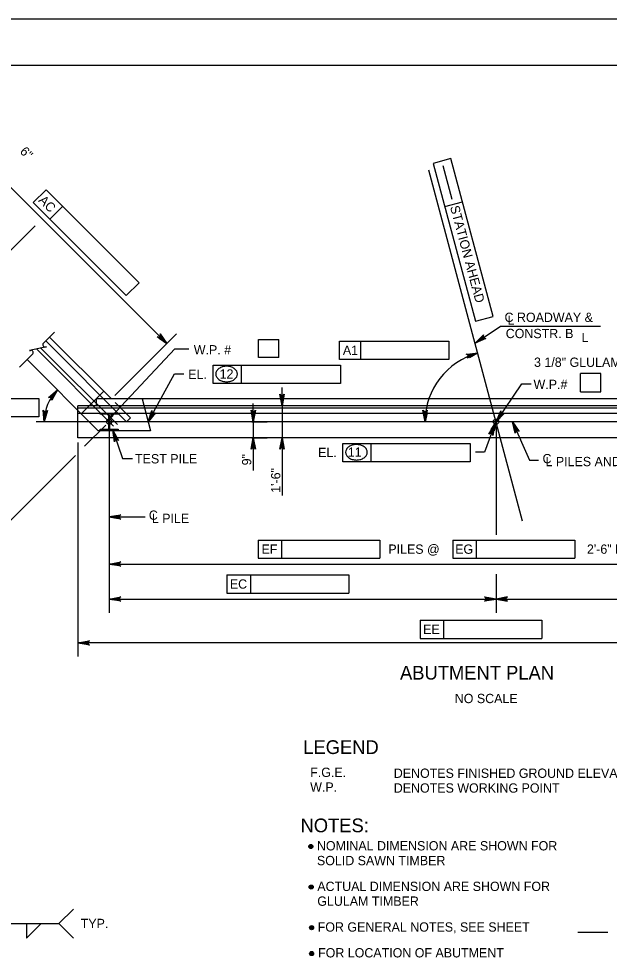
# Model space of a CAD drawing. Extents: x 638304 to 640306, y 296653 to 298435.
# Drawn here: x 639455.2 to 639645.7, y 298131.6 to 298435.5 of the extents above; entities that cross this region are included whole.
import ezdxf

# ---------------------------------------------------------------- set-up
doc = ezdxf.new("R2010")
doc.units = 0
for name, color, linetype in [('2', 7, 'Continuous'), ('3', 7, 'Continuous'), ('4', 7, 'Continuous'), ('5', 7, 'Continuous'), ('Level 2', 7, 'Continuous'), ('Level 3', 7, 'Continuous'), ('Level 4', 7, 'Continuous'), ('Level 5', 7, 'Continuous'), ('Level 6', 7, 'Continuous'), ('Level 8', 7, 'Continuous'), ('PLT-BNDY', 7, 'Continuous')]:
    doc.layers.add(name, color=color, linetype=linetype)

# ---------------------------------------------------------------- blocks, each defined once
blk = doc.blocks.new('HPILE')
at = {"layer": '3'}
for p, q in [((-0.12, -2.66), (-0.12, 2.66)), ((0.12, 2.66), (0.12, -2.66)), ((-3.67, -3.1), (-0.56, -3.1))]:
    blk.add_line(p, q, dxfattribs=at)
for points in [[(-0.56, 3.1), (-3.67, 3.1), (-3.67, 3.54), (3.67, 3.54), (3.67, 3.1), (0.56, 3.1)], [(0.56, -3.1), (3.67, -3.1), (3.67, -3.54), (-3.67, -3.54), (-3.67, -3.1)]]:
    blk.add_lwpolyline(points, dxfattribs=at)
for centre, start, end in [((-0.56, 2.66), 0, 90), ((0.56, 2.66), 90, 180), ((-0.56, -2.66), 270, 0), ((0.56, -2.66), 180, 270)]:
    blk.add_arc(centre, 0.438, start, end, dxfattribs=at)

msp = doc.modelspace()

# ---------------------------------------------------------------- linework, layer by layer
at = {"layer": '2'}
msp.add_line((639316.46, 298420.46), (640102.46, 298420.46), dxfattribs=at)
at = {"layer": 'Level 2'}
for p, q in [((639485.08, 298312.79), (639465.12, 298332.75)), ((639480.8, 298302.48), (639457.82, 298325.46)), ((639482.64, 298315.23), (639475.35, 298307.93)), ((639731.17, 298312.79), (639485.08, 298312.79)), ((639494.95, 298312.79), (639497.71, 298302.48)), ((639474.26, 298300.27), (639474.26, 298309.02)), ((639489.95, 298305.43), (639491.17, 298306.64)), ((639743.13, 298300.27), (639474.26, 298300.27)), ((639497.71, 298302.48), (639480.8, 298302.48))]:
    msp.add_line(p, q, dxfattribs=at)
at = {"layer": 'Level 3'}
for p, q in [((639489.95, 298305.43), (639463.9, 298331.54)), ((639480.2, 298310.58), (639480.2, 298312.79)), ((639485.08, 298312.79), (639480.2, 298312.79)), ((639474.26, 298309.02), (639474.26, 298310.58)), ((639743.13, 298310.58), (639474.26, 298310.58)), ((639474.26, 298309.93), (639743.13, 298309.93)), ((639486.22, 298311.65), (639491.17, 298306.64)), ((639474.26, 298308.21), (639743.13, 298308.21)), ((639468.07, 298143.43), (639472.77, 298148.13)), ((639438.49, 298143.44), (639468.07, 298143.44)), ((639457.64, 298143.44), (639457.64, 298138.74)), ((639457.64, 298138.74), (639462.34, 298143.44)), ((639468.07, 298143.43), (639472.77, 298138.74))]:
    msp.add_line(p, q, dxfattribs=at)
msp.add_circle((639609.2, 298305.43), 0.849, dxfattribs=at)
at = {"layer": 'Level 4'}
for p, q in [((639502.92, 298330.64), (639443.7, 298389.87)), ((639594.61, 298390.33), (639588.91, 298388.8)), ((639588.91, 298388.8), (639602.57, 298337.85)), ((639595.09, 298377.11), (639592.16, 298388.03)), ((639608.26, 298339.38), (639594.61, 298390.33)), ((639464.01, 298380.29), (639459.84, 298376.12)), ((639464.01, 298380.29), (639494.02, 298350.28)), ((639459.84, 298376.12), (639489.85, 298346.11)), ((639592.64, 298374.91), (639598.33, 298376.44)), ((639469.35, 298374.95), (639465.18, 298370.78)), ((639444.8, 298353.07), (639460.41, 298368.69)), ((639494.02, 298350.28), (639489.85, 298346.11)), ((639602.57, 298337.85), (639608.26, 298339.38)), ((639602.44, 298330.81), (639610.62, 298336.28)), ((639610.62, 298336.28), (639642.86, 298336.28)), ((639486.16, 298313.88), (639506.05, 298333.77)), ((639532.56, 298332), (639539.14, 298332)), ((639532.56, 298326.1), (639532.56, 298332)), ((639539.14, 298326.1), (639539.14, 298332)), ((639558.71, 298331.4), (639593.95, 298331.4)), ((639558.71, 298325.51), (639558.71, 298331.4)), ((639565.54, 298325.51), (639565.54, 298331.4)), ((639593.95, 298331.4), (639593.95, 298325.51)), ((639485.76, 298304), (639460.88, 298328.89)), ((639486.99, 298304.52), (639462.29, 298329.21)), ((639486.16, 298313.88), (639497.84, 298325.56)), ((639539.14, 298326.1), (639532.56, 298326.1)), ((639593.95, 298325.51), (639558.71, 298325.51)), ((639517.88, 298323.64), (639559.01, 298323.64)), ((639517.88, 298317.75), (639517.88, 298323.64)), ((639527.03, 298317.75), (639527.03, 298323.64)), ((639559.01, 298323.64), (639559.01, 298317.75)), ((639496.93, 298305.4), (639505.47, 298320.86)), ((639505.47, 298320.86), (639508.42, 298320.86)), ((639643.06, 298320.93), (639636.48, 298320.93)), ((639636.48, 298315.04), (639636.48, 298320.93)), ((639643.06, 298315.04), (639643.06, 298320.93)), ((639559.01, 298317.75), (639517.88, 298317.75)), ((639540.14, 298313.53), (639540.14, 298316.48)), ((639636.48, 298315.04), (639643.06, 298315.04)), ((639426.36, 298312.93), (639461.6, 298312.93)), ((639461.6, 298312.93), (639461.6, 298307.03)), ((639530.86, 298308.37), (639530.86, 298311.32)), ((639539.57, 298310.58), (639535.72, 298310.58)), ((639540.14, 298310.58), (639540.14, 298300.27)), ((639461.6, 298307.03), (639426.36, 298307.03)), ((639755.33, 298305.43), (639460.73, 298305.43)), ((639483.26, 298304.34), (639476.42, 298297.5)), ((639484.34, 298303.89), (639484.34, 298243.75)), ((639530.36, 298305.43), (639535.28, 298305.43)), ((639530.86, 298305.43), (639530.86, 298300.27)), ((639608.84, 298304.66), (639605.46, 298295.62)), ((639609.21, 298303.89), (639609.21, 298268.88)), ((639530.36, 298300.27), (639535.28, 298300.27)), ((639539.57, 298300.27), (639535.72, 298300.27)), ((639474.26, 298298.73), (639474.26, 298229.63)), ((639530.86, 298297.32), (639530.86, 298289.66)), ((639540.14, 298297.32), (639540.14, 298281.64)), ((639559.77, 298298.4), (639600.9, 298298.4)), ((639559.77, 298292.51), (639559.77, 298298.4)), ((639568.92, 298292.51), (639568.92, 298298.4)), ((639600.9, 298298.4), (639600.9, 298292.51)), ((639473.45, 298294.53), (639445.7, 298266.78)), ((639605.46, 298295.62), (639602.52, 298295.62)), ((639600.9, 298292.51), (639559.77, 298292.51)), ((639484.34, 298274.68), (639495.93, 298274.68)), ((639532.39, 298267.23), (639532.39, 298261.34)), ((639532.39, 298267.23), (639571.68, 298267.23)), ((639539.93, 298267.23), (639539.93, 298261.34)), ((639571.68, 298267.23), (639571.68, 298261.34)), ((639595.28, 298267.23), (639634.58, 298267.23)), ((639595.28, 298267.23), (639595.28, 298261.34)), ((639602.83, 298267.23), (639602.83, 298261.34)), ((639634.58, 298267.23), (639634.58, 298261.34)), ((639532.39, 298261.34), (639571.68, 298261.34)), ((639595.28, 298261.34), (639634.58, 298261.34)), ((639484.34, 298259.48), (639731.9, 298259.48)), ((639522.35, 298255.98), (639561.65, 298255.98)), ((639522.35, 298255.98), (639522.35, 298250.08)), ((639529.9, 298255.98), (639529.9, 298250.08)), ((639561.65, 298255.98), (639561.65, 298250.08)), ((639609.21, 298256.17), (639609.21, 298243.75)), ((639484.34, 298248.17), (639606.26, 298248.17)), ((639522.35, 298250.08), (639561.65, 298250.08)), ((639612.15, 298248.17), (639731.9, 298248.17)), ((639584.67, 298241.36), (639623.96, 298241.36)), ((639584.67, 298241.36), (639584.67, 298235.46)), ((639592.21, 298241.36), (639592.21, 298235.46)), ((639623.96, 298241.36), (639623.96, 298235.46)), ((639743.13, 298234.05), (639474.26, 298234.05)), ((639584.67, 298235.46), (639623.96, 298235.46)), ((639635.64, 298140.62), (639645.28, 298140.62))]:
    msp.add_line(p, q, dxfattribs=at)
for points in [[(639502.92, 298330.64), (639499.8, 298332.78), (639500.14, 298332.72), (639500.43, 298332.79), (639500.63, 298332.94), (639500.78, 298333.14), (639500.85, 298333.43), (639500.79, 298333.77), (639502.92, 298330.64), (639500.85, 298333.43), (639500.78, 298333.14), (639502.92, 298330.64), (639500.63, 298332.94), (639500.43, 298332.79), (639502.92, 298330.64), (639500.14, 298332.72)], [(639602.44, 298330.81), (639605.14, 298333.46), (639605.02, 298333.14), (639605.03, 298332.85), (639605.13, 298332.62), (639605.31, 298332.43), (639605.57, 298332.31), (639605.92, 298332.3), (639602.44, 298330.81), (639605.57, 298332.31), (639605.31, 298332.43), (639602.44, 298330.81), (639605.13, 298332.62), (639605.03, 298332.85), (639602.44, 298330.81), (639605.02, 298333.14)], [(639483.45, 298305.43), (639505.54, 298328.9), (639510.03, 298328.9)], [(639603.31, 298327.52), (639599.9, 298325.89), (639600.12, 298326.16), (639600.2, 298326.44), (639600.18, 298326.69), (639600.07, 298326.92), (639599.87, 298327.13), (639599.54, 298327.24), (639603.31, 298327.52), (639599.87, 298327.13), (639600.07, 298326.92), (639603.31, 298327.52), (639600.18, 298326.69), (639600.2, 298326.44), (639603.31, 298327.52), (639600.12, 298326.16)], [(639467.61, 298315.68), (639465.81, 298312.34), (639465.84, 298312.69), (639465.74, 298312.96), (639465.57, 298313.15), (639465.35, 298313.27), (639465.06, 298313.32), (639464.73, 298313.22), (639467.61, 298315.68), (639465.06, 298313.32), (639465.35, 298313.27), (639467.61, 298315.68), (639465.57, 298313.15), (639465.74, 298312.96), (639467.61, 298315.68), (639465.84, 298312.69)], [(639609.21, 298305.43), (639617.51, 298317.63), (639620.53, 298317.63)], [(639540.14, 298310.58), (639539.44, 298314.31), (639539.64, 298314.02), (639539.89, 298313.87), (639540.14, 298313.83), (639540.39, 298313.87), (639540.64, 298314.02), (639540.84, 298314.31), (639540.14, 298310.58), (639540.64, 298314.02), (639540.39, 298313.87), (639540.14, 298310.58), (639540.14, 298313.83), (639539.89, 298313.87), (639540.14, 298310.58), (639539.64, 298314.02)], [(639463.36, 298305.43), (639463.06, 298309.2), (639463.23, 298308.89), (639463.46, 298308.72), (639463.7, 298308.65), (639463.96, 298308.67), (639464.22, 298308.79), (639464.45, 298309.05), (639463.36, 298305.43), (639464.22, 298308.79), (639463.96, 298308.67), (639463.36, 298305.43), (639463.7, 298308.65), (639463.46, 298308.72), (639463.36, 298305.43), (639463.23, 298308.89)], [(639496.93, 298305.4), (639498.11, 298309), (639498.15, 298308.65), (639498.3, 298308.4), (639498.5, 298308.24), (639498.73, 298308.16), (639499.02, 298308.17), (639499.34, 298308.32), (639496.93, 298305.4), (639499.02, 298308.17), (639498.73, 298308.16), (639496.93, 298305.4), (639498.5, 298308.24), (639498.3, 298308.4), (639496.93, 298305.4), (639498.15, 298308.65)], [(639530.86, 298305.43), (639530.16, 298309.15), (639530.36, 298308.86), (639530.61, 298308.71), (639530.86, 298308.67), (639531.11, 298308.71), (639531.36, 298308.86), (639531.56, 298309.15), (639530.86, 298305.43), (639531.36, 298308.86), (639531.11, 298308.71), (639530.86, 298305.43), (639530.86, 298308.67), (639530.61, 298308.71), (639530.86, 298305.43), (639530.36, 298308.86)], [(639586.3, 298305.43), (639585.61, 298309.15), (639585.81, 298308.86), (639586.06, 298308.71), (639586.3, 298308.67), (639586.55, 298308.71), (639586.8, 298308.86), (639587, 298309.15), (639586.3, 298305.43), (639586.8, 298308.86), (639586.55, 298308.71), (639586.3, 298305.43), (639586.3, 298308.67), (639586.06, 298308.71), (639586.3, 298305.43), (639585.81, 298308.86)], [(639609.21, 298305.43), (639610.72, 298308.89), (639610.73, 298308.55), (639610.85, 298308.28), (639611.03, 298308.11), (639611.26, 298308), (639611.55, 298307.99), (639611.87, 298308.11), (639609.21, 298305.43), (639611.55, 298307.99), (639611.26, 298308), (639609.21, 298305.43), (639611.03, 298308.11), (639610.85, 298308.28), (639609.21, 298305.43), (639610.73, 298308.55)], [(639608.84, 298304.66), (639608.19, 298300.93), (639608.11, 298301.27), (639607.92, 298301.49), (639607.7, 298301.62), (639607.45, 298301.67), (639607.17, 298301.62), (639606.88, 298301.42), (639608.84, 298304.66), (639607.17, 298301.62), (639607.45, 298301.67), (639608.84, 298304.66), (639607.7, 298301.62), (639607.92, 298301.49), (639608.84, 298304.66), (639608.11, 298301.27)], [(639614.56, 298305.43), (639619.97, 298293), (639622.91, 298293)], [(639614.56, 298305.43), (639616.68, 298302.29), (639616.39, 298302.47), (639616.1, 298302.51), (639615.85, 298302.45), (639615.64, 298302.31), (639615.47, 298302.08), (639615.4, 298301.73), (639614.56, 298305.43), (639615.47, 298302.08), (639615.64, 298302.31), (639614.56, 298305.43), (639615.85, 298302.45), (639616.1, 298302.51), (639614.56, 298305.43), (639616.39, 298302.47)], [(639485.52, 298302.65), (639488.62, 298293.55), (639491.83, 298293.55)], [(639485.52, 298302.65), (639487.38, 298299.35), (639487.1, 298299.56), (639486.82, 298299.62), (639486.57, 298299.58), (639486.34, 298299.46), (639486.16, 298299.24), (639486.06, 298298.9), (639485.52, 298302.65), (639486.16, 298299.24), (639486.34, 298299.46), (639485.52, 298302.65), (639486.57, 298299.58), (639486.82, 298299.62), (639485.52, 298302.65), (639487.1, 298299.56)], [(639530.86, 298300.27), (639531.56, 298296.55), (639531.36, 298296.83), (639531.11, 298296.98), (639530.86, 298297.02), (639530.61, 298296.98), (639530.36, 298296.83), (639530.16, 298296.55), (639530.86, 298300.27), (639530.36, 298296.83), (639530.61, 298296.98), (639530.86, 298300.27), (639530.86, 298297.02), (639531.11, 298296.98), (639530.86, 298300.27), (639531.36, 298296.83)], [(639540.14, 298300.27), (639540.84, 298296.55), (639540.64, 298296.83), (639540.39, 298296.98), (639540.14, 298297.02), (639539.89, 298296.98), (639539.64, 298296.83), (639539.44, 298296.55), (639540.14, 298300.27), (639539.64, 298296.83), (639539.89, 298296.98), (639540.14, 298300.27), (639540.14, 298297.02), (639540.39, 298296.98), (639540.14, 298300.27), (639540.64, 298296.83)], [(639484.34, 298274.68), (639488.06, 298275.38), (639487.78, 298275.18), (639487.63, 298274.93), (639487.59, 298274.68), (639487.63, 298274.43), (639487.78, 298274.19), (639488.06, 298273.99), (639484.34, 298274.68), (639487.78, 298274.19), (639487.63, 298274.43), (639484.34, 298274.68), (639487.59, 298274.68), (639487.63, 298274.93), (639484.34, 298274.68), (639487.78, 298275.18)], [(639484.34, 298259.48), (639488.06, 298260.18), (639487.78, 298259.98), (639487.63, 298259.73), (639487.59, 298259.48), (639487.63, 298259.23), (639487.78, 298258.98), (639488.06, 298258.78), (639484.34, 298259.48), (639487.78, 298258.98), (639487.63, 298259.23), (639484.34, 298259.48), (639487.59, 298259.48), (639487.63, 298259.73), (639484.34, 298259.48), (639487.78, 298259.98)], [(639484.34, 298248.17), (639488.06, 298248.87), (639487.78, 298248.67), (639487.63, 298248.42), (639487.59, 298248.17), (639487.63, 298247.92), (639487.78, 298247.67), (639488.06, 298247.47), (639484.34, 298248.17), (639487.78, 298247.67), (639487.63, 298247.92), (639484.34, 298248.17), (639487.59, 298248.17), (639487.63, 298248.42), (639484.34, 298248.17), (639487.78, 298248.67)], [(639609.21, 298248.17), (639605.48, 298247.47), (639605.77, 298247.67), (639605.92, 298247.92), (639605.96, 298248.17), (639605.92, 298248.42), (639605.77, 298248.67), (639605.48, 298248.87), (639609.21, 298248.17), (639605.77, 298248.67), (639605.92, 298248.42), (639609.21, 298248.17), (639605.96, 298248.17), (639605.92, 298247.92), (639609.21, 298248.17), (639605.77, 298247.67)], [(639609.21, 298248.17), (639612.93, 298247.47), (639612.64, 298247.67), (639612.49, 298247.92), (639612.45, 298248.17), (639612.49, 298248.42), (639612.64, 298248.67), (639612.93, 298248.87), (639609.21, 298248.17), (639612.64, 298248.67), (639612.49, 298248.42), (639609.21, 298248.17), (639612.45, 298248.17), (639612.49, 298247.92), (639609.21, 298248.17), (639612.64, 298247.67)], [(639474.26, 298234.05), (639477.98, 298234.75), (639477.7, 298234.55), (639477.55, 298234.3), (639477.5, 298234.05), (639477.55, 298233.8), (639477.7, 298233.55), (639477.98, 298233.35), (639474.26, 298234.05), (639477.7, 298233.55), (639477.55, 298233.8), (639474.26, 298234.05), (639477.5, 298234.05), (639477.55, 298234.3), (639474.26, 298234.05), (639477.7, 298234.55)]]:
    msp.add_lwpolyline(points, dxfattribs=at)
for points in [[(639501.19, 298333.07), (639500.49, 298332.38), (639502.92, 298330.64)], [(639604.61, 298332.86), (639605.16, 298332.04), (639602.44, 298330.81)], [(639600.61, 298326.09), (639600.3, 298327.02), (639603.25, 298327.5)], [(639539.64, 298313.53), (639540.63, 298313.53), (639540.14, 298310.58)], [(639483.45, 298305.43), (639485.65, 298307.41), (639485.29, 298307.74)], [(639497.88, 298308.15), (639498.74, 298307.68), (639496.89, 298305.34)], [(639530.37, 298308.37), (639531.35, 298308.37), (639530.86, 298305.43)], [(639586.01, 298308.4), (639586.98, 298308.33), (639586.3, 298305.43)], [(639609.21, 298305.43), (639611.07, 298307.73), (639610.66, 298308)], [(639608.56, 298302.51), (639607.65, 298302.88), (639609.21, 298305.43)], [(639614.56, 298305.43), (639615.51, 298302.62), (639615.96, 298302.82)], [(639485.52, 298302.65), (639486.24, 298299.78), (639486.7, 298299.94)], [(639530.37, 298297.32), (639531.35, 298297.32), (639530.86, 298300.27)], [(639539.64, 298297.32), (639540.63, 298297.32), (639540.14, 298300.27)], [(639487.29, 298274.19), (639487.29, 298275.17), (639484.34, 298274.68)], [(639487.29, 298259.97), (639487.29, 298258.99), (639484.34, 298259.48)], [(639487.29, 298248.66), (639487.29, 298247.68), (639484.34, 298248.17)], [(639606.26, 298248.66), (639606.26, 298247.68), (639609.21, 298248.17)], [(639612.15, 298248.66), (639612.15, 298247.68), (639609.21, 298248.17)], [(639477.21, 298234.54), (639477.21, 298233.56), (639474.26, 298234.05)]]:
    msp.add_lwpolyline(points, close=True, dxfattribs=at)
for centre, radius in [((639484.34, 298305.43), 0.849), ((639549.41, 298168.32), 0.665), ((639549.41, 298168.32), 0.499), ((639549.41, 298168.32), 0.333), ((639549.41, 298168.32), 0.166), ((639549.54, 298155.22), 0.665), ((639549.54, 298155.22), 0.499), ((639549.54, 298155.22), 0.333), ((639549.54, 298155.22), 0.166), ((639549.66, 298142.11), 0.665), ((639549.66, 298142.11), 0.499), ((639549.66, 298142.11), 0.333), ((639549.66, 298142.11), 0.166), ((639549.66, 298133.76), 0.665), ((639549.66, 298133.76), 0.499), ((639549.66, 298133.76), 0.333), ((639549.66, 298133.76), 0.166)]:
    msp.add_circle(centre, radius, dxfattribs=at)
for centre, radius, start, end in [((639609.16, 298305.43), 22.86, 104.8222, 180.0009), ((639520.57, 298320.8), 1.82, 149.9767, 180), ((639521.37, 298320.34), 2.75, 125.6316, 149.9767), ((639521.9, 298319.61), 3.65, 106.5358, 125.6316), ((639522.24, 298318.45), 4.86, 90, 106.5358), ((639522.24, 298318.45), 4.86, 73.4642, 90), ((639522.59, 298319.61), 3.65, 54.3684, 73.4642), ((639523.11, 298320.34), 2.75, 30.0233, 54.3684), ((639523.92, 298320.8), 1.82, 0, 30.0233), ((639520.57, 298320.8), 1.82, 180, 210.0233), ((639521.37, 298321.27), 2.75, 210.0233, 234.3684), ((639521.9, 298322), 3.65, 234.3684, 253.4642), ((639522.24, 298323.16), 4.86, 253.4642, 270), ((639522.24, 298323.16), 4.86, 270, 286.5358), ((639522.59, 298322), 3.65, 286.5358, 305.6316), ((639523.11, 298321.27), 2.75, 305.6316, 329.9767), ((639523.92, 298320.8), 1.82, 329.9767, 0), ((639477.86, 298305.43), 14.5, 134.9989, 180.0015), ((639563.27, 298295.1), 2.75, 125.6316, 149.9767), ((639563.79, 298294.36), 3.65, 106.5358, 125.6316), ((639564.14, 298293.2), 4.86, 90, 106.5358), ((639564.14, 298293.2), 4.86, 73.4642, 90), ((639564.48, 298294.36), 3.65, 54.3684, 73.4642), ((639565.01, 298295.1), 2.75, 30.0233, 54.3684), ((639562.47, 298295.56), 1.82, 149.9767, 180), ((639562.47, 298295.56), 1.82, 180, 210.0233), ((639563.27, 298296.02), 2.75, 210.0233, 234.3684), ((639563.79, 298296.76), 3.65, 234.3684, 253.4642), ((639564.48, 298296.76), 3.65, 286.5358, 305.6316), ((639565.01, 298296.02), 2.75, 305.6316, 329.9767), ((639565.81, 298295.56), 1.82, 0, 30.0233), ((639565.81, 298295.56), 1.82, 329.9767, 0), ((639564.14, 298297.92), 4.86, 253.4642, 270), ((639564.14, 298297.92), 4.86, 270, 286.5358)]:
    msp.add_arc(centre, radius, start, end, dxfattribs=at)
at = {"layer": 'Level 6'}
msp.add_line((639617.75, 298273.36), (639587.55, 298386.64), dxfattribs=at)
at = {"layer": 'Level 8'}
for p, q in [((639466.68, 298334.32), (639463.1, 298330.74)), ((639459.67, 298327.31), (639455.36, 298323))]:
    msp.add_line(p, q, dxfattribs=at)
msp.add_lwpolyline([(639463.78, 298329.55), (639464.13, 298329.63), (639458.6, 298328.37), (639458.97, 298328.45)], dxfattribs=at)
for centre, start, end in [((639463.6, 298330.24), 135, 285), ((639459.13, 298327.76), 320.3286, 102.8672)]:
    msp.add_arc(centre, 0.709, start, end, dxfattribs=at)
at = {"layer": 'PLT-BNDY'}
msp.add_lwpolyline([(639276.46, 298435.46), (640117.46, 298435.46), (640117.46, 297841.46), (639276.46, 297841.46)], close=True, dxfattribs=at)

# ---------------------------------------------------------------- block references
at = {"layer": 'Level 3', "xscale": 0.7859001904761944, "yscale": 0.7859001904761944}
msp.add_blockref('HPILE', (639484.34, 298305.43), dxfattribs=at)

# ---------------------------------------------------------------- texts
at = {"layer": '4'}
for s, height, p in [('ABUTMENT PLAN', 4.4294, (639578.21, 298222.19)), ('NO SCALE', 3, (639595.88, 298214.59)), ('NOTES:', 4.429, (639546.1, 298172.92))]:
    msp.add_text(s, height=height, dxfattribs=at).set_placement(p)
at = {"layer": '5'}
msp.add_text('LEGEND', height=4.429, dxfattribs=at).set_placement((639546.98, 298198.17))
at = {"layer": 'Level 4'}
for s, height, rotation, p in [('AC', 3, 314.9382, (639461.35, 298376.66)), ('STATION AHEAD', 3.0001, 285, (639594.33, 298374.74))]:
    msp.add_text(s, height=height, rotation=rotation, dxfattribs=at).set_placement(p)
for s, height, p in [('C ROADWAY &', 3.0001, (639611.94, 298337.62)), ('L', 3, (639612.9, 298336.69)), ('CONSTR. B', 3, (639612.33, 298332.39)), ('L', 3, (639636.81, 298331.1)), ('W.P. # ', 3, (639511.65, 298327.13)), ('A1', 3, (639559.77, 298326.99)), ('EL.', 3, (639509.87, 298319.23)), ('12', 3, (639519.98, 298319.34)), ('W.P.#', 3, (639621.3, 298315.97)), ('EL.', 3, (639551.76, 298293.99)), ('11', 3, (639561.35, 298294.1)), ('TEST PILE', 3, (639492.69, 298291.96)), ('C', 3, (639624.2, 298292.01)), ('L PILES AND BEARING SILL', 3.0001, (639625.16, 298291.07)), ('C', 3, (639497.14, 298273.76)), ('L PILE', 3, (639498.11, 298272.72)), ('EF', 3, (639533.5, 298262.79)), ('PILES @', 3, (639574.44, 298262.79)), ('EG', 3, (639596.01, 298262.79)), ('2\'-6" MIN. SPACING', 3.0001, (639638.53, 298262.79)), ('EC', 3, (639523.28, 298251.53)), ('EE', 3, (639585.67, 298236.91)), ('NOMINAL DIMENSION ARE SHOWN FOR ', 3.0001, (639551.39, 298167.05)), ('SOLID SAWN TIMBER', 3.0001, (639551.39, 298162.28)), ('ACTUAL DIMENSION ARE SHOWN FOR ', 3.0001, (639551.51, 298153.95)), ('GLULAM TIMBER', 3.0001, (639551.51, 298149.18)), ('TYP.', 3, (639475.15, 298141.97)), ('FOR GENERAL NOTES, SEE SHEET    ', 3.0001, (639551.64, 298140.84)), ('FOR LOCATION OF ABUTMENT', 3.0001, (639551.76, 298132.51))]:
    msp.add_text(s, height=height, dxfattribs=at).set_placement(p)
at = {"layer": 'Level 5'}
for s, rotation, p in [('6"', 315, (639455.31, 298392.41)), ('9"', 90, (639530.21, 298291.34)), ('1\'-6"', 90, (639539.59, 298282.48))]:
    msp.add_text(s, height=3, rotation=rotation, dxfattribs=at).set_placement(p)
for s, height, p in [('3 1/8" GLULAM BACKWALL', 3.0001, (639621.46, 298323.12)), ('F.G.E.', 3, (639549.21, 298190.76)), ('DENOTES FINISHED GROUND ELEVATION', 3.0001, (639576.2, 298190.47)), ('W.P.', 3, (639549.21, 298185.99)), ('DENOTES WORKING POINT', 3.0001, (639576.2, 298185.7))]:
    msp.add_text(s, height=height, dxfattribs=at).set_placement(p)

doc.saveas('drawing.dxf')
